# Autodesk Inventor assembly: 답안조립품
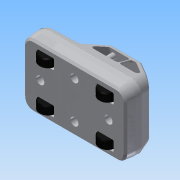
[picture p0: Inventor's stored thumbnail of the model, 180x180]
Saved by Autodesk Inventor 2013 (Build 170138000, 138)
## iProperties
Created: 2015-05
Part Number: 답안조립품
Document SubType Name: Assembly
Designer: Administrator
Author: Administrator
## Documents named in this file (7)
- C:\Documents and Settings\Administrator\바탕 화면\450507V1019\답안조립품.iam
- C:\Documents and Settings\Administrator\바탕 화면\450507V1019\1-본체.ipt
- C:\Documents and Settings\Administrator\바탕 화면\450507V1019\커버.ipt
- C:\Documents and Settings\Administrator\바탕 화면\450507V1019\바퀴.ipt
- C:\Documents and Settings\Administrator\바탕 화면\450507V1019\바퀴고정부.ipt
- C:\Documents and Settings\Administrator\바탕 화면\450507V1019\M2x4.ipt
- C:\Documents and Settings\Administrator\바탕 화면\450507V1019\M4x10.ipt
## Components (21 placed, 3 different names)
1. 1-본체:1
2. M2x4:1
3. M2x4:2
4. M2x4:3
5. M2x4:4
6. M2x4:5
7. M2x4:6
8. M2x4:7
9. M2x4:8
10. M2x4:9
11. M2x4:10
12. M2x4:11
13. M2x4:12
14. M2x4:13
15. M2x4:14
16. M2x4:15
17. M2x4:16
18. M4x10:1
19. M4x10:2
20. M4x10:3
21. M4x10:4
